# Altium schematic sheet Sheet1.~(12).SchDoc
size A3
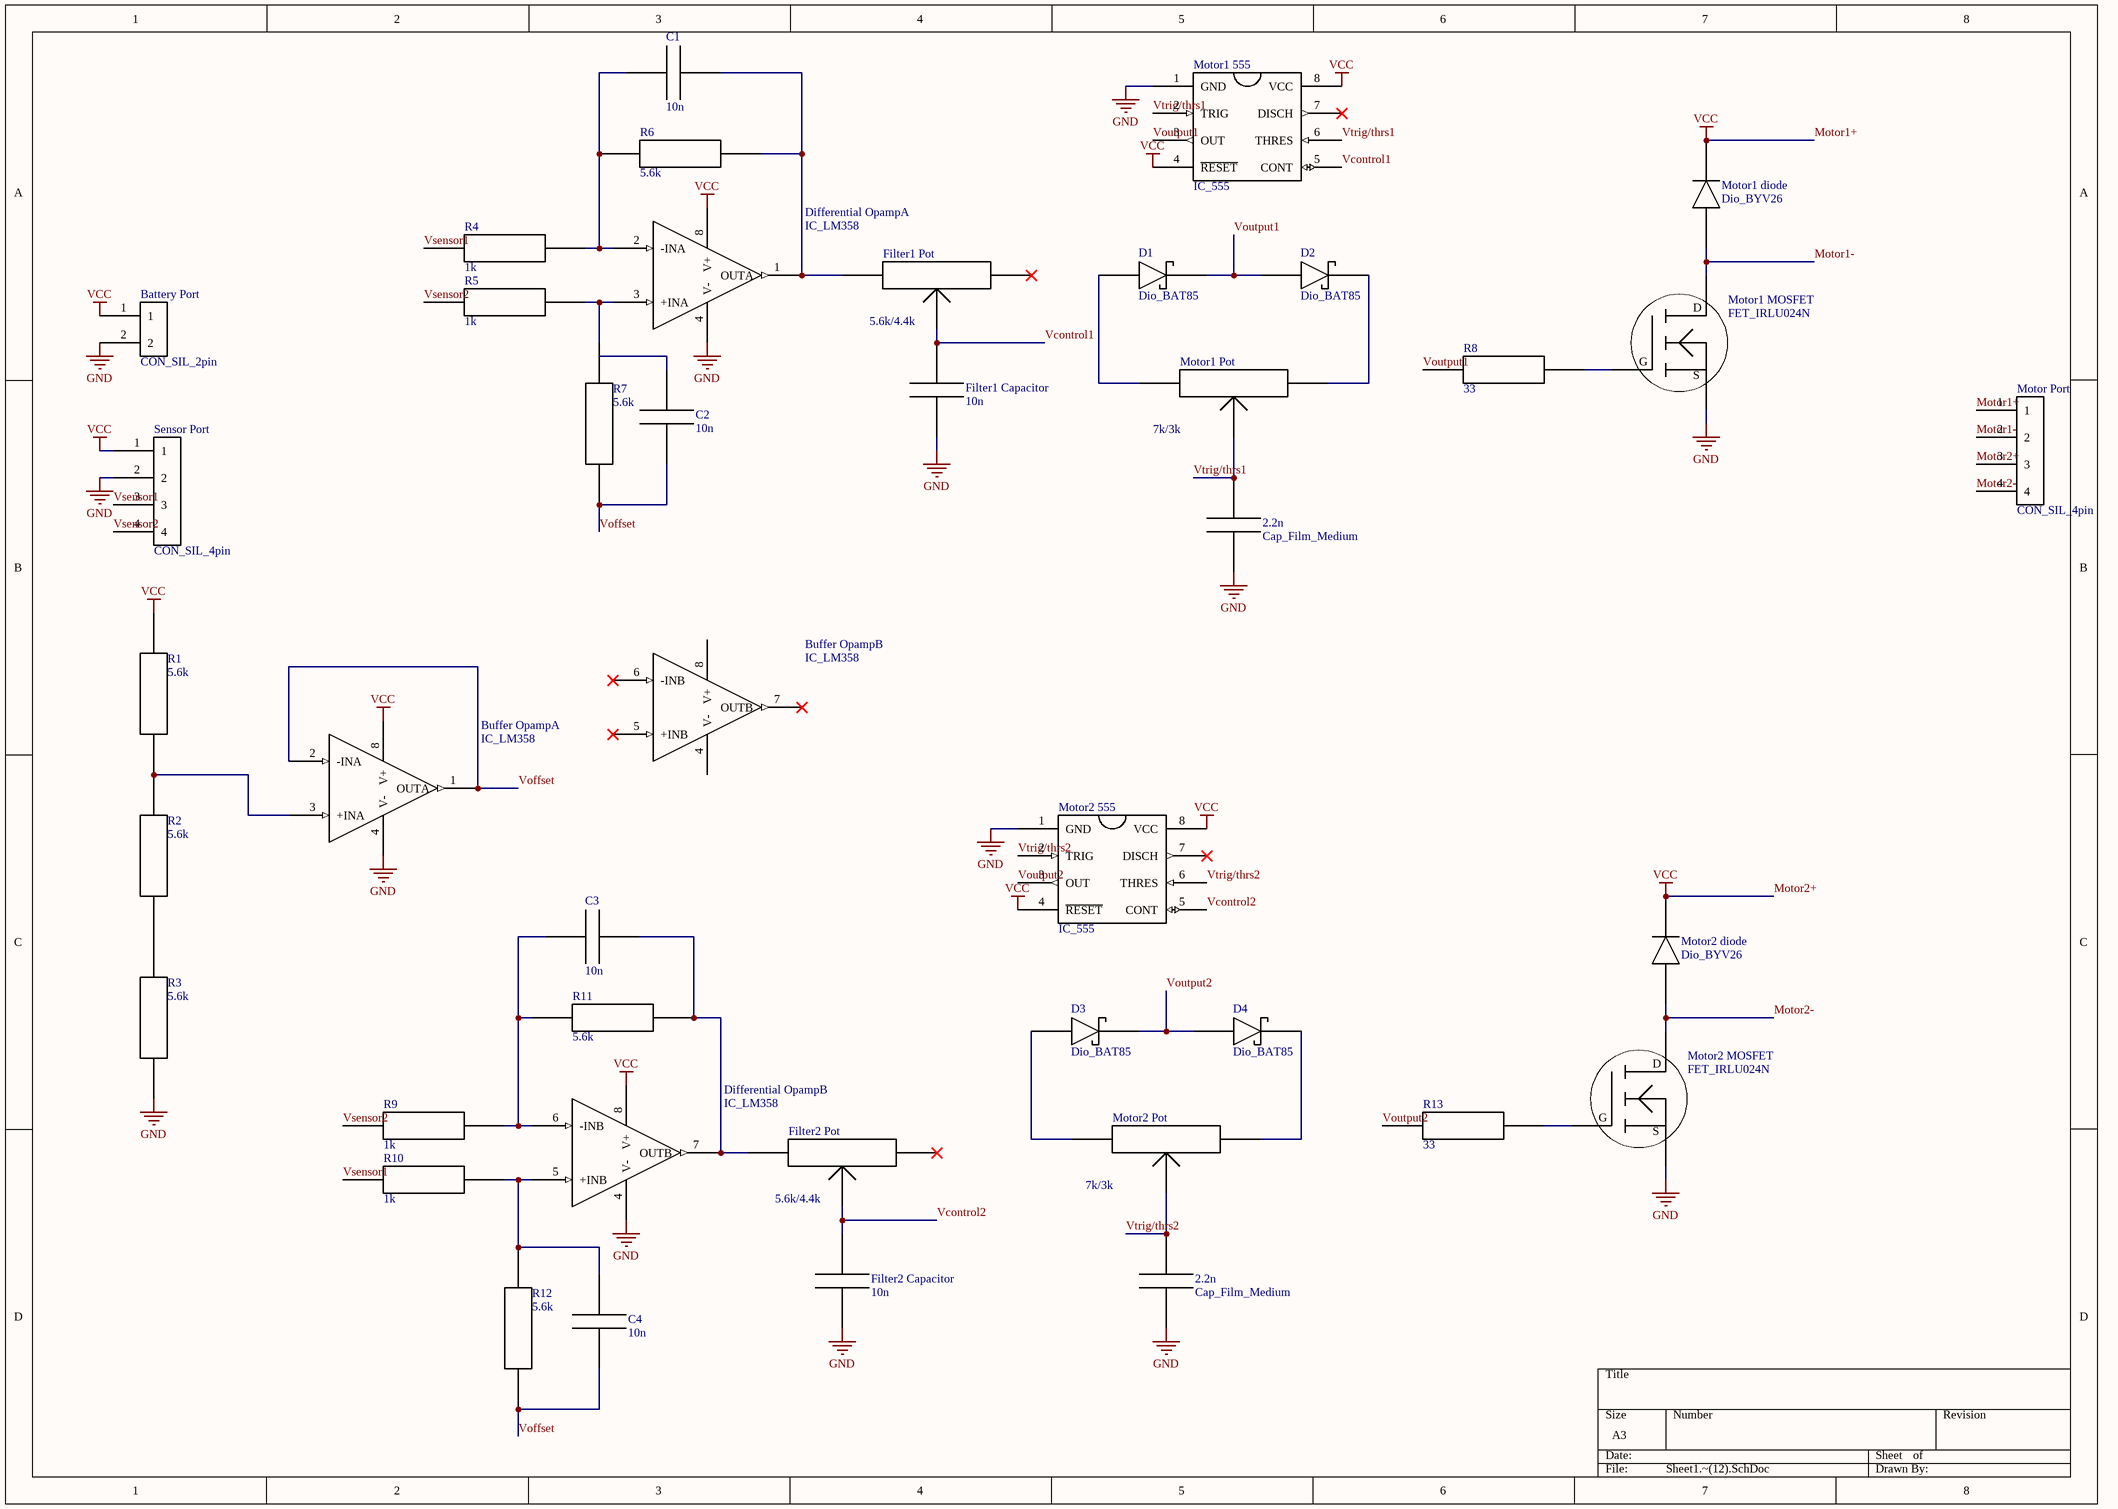
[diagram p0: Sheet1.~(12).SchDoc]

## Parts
(Parts that share a designator on the sheet are numbered #1, #2 ... from top to bottom, then left to right.)
2.2n#1  Cap_Film_Medium  [CAP_FILM_3.2mm]
2.2n#2  Cap_Film_Medium  [CAP_FILM_3.2mm]
Battery_Port  CON_SIL_2pin  [ece-HDR1X2]
Buffer_Opamp  IC_LM358  [DIP_8]  (parts A,B of 2)
C1  10n  [CAP_FILM_3.2mm]
C2  10n  [CAP_FILM_3.2mm]
C3  10n  [CAP_FILM_3.2mm]
C4  10n  [CAP_FILM_3.2mm]
D1  Dio_BAT85  [Diode_SmallSignal]
D2  Dio_BAT85  [Diode_SmallSignal]
D3  Dio_BAT85  [Diode_SmallSignal]
D4  Dio_BAT85  [Diode_SmallSignal]
Differential_Opamp  IC_LM358  [DIP_8]  (parts A,B of 2)
Filter1_Capacitor  10n  [CAP_FILM_3.2mm]
Filter1_Pot  5.6k/4.4k  [POT]
Filter2_Capacitor  10n  [CAP_FILM_3.2mm]
Filter2_Pot  5.6k/4.4k  [POT]
Motor1_555  IC_555  [DIP_8]
Motor1_diode  Dio_BYV26  [SOD_47]
Motor1_MOSFET  FET_IRLU024N  [TO_251AA]
Motor1_Pot  7k/3k  [POT]
Motor2_555  IC_555  [DIP_8]
Motor2_diode  Dio_BYV26  [SOD_47]
Motor2_MOSFET  FET_IRLU024N  [TO_251AA]
Motor2_Pot  7k/3k  [POT]
Motor_Port  CON_SIL_4pin  [ece-HDR1X4]
R1  5.6k  [Resistor_400mil_pitch]
R2  5.6k  [Resistor_400mil_pitch]
R3  5.6k  [Resistor_400mil_pitch]
R4  1k  [Resistor_400mil_pitch]
R5  1k  [Resistor_400mil_pitch]
R6  5.6k  [Resistor_400mil_pitch]
R7  5.6k  [Resistor_400mil_pitch]
R8  33  [Resistor_400mil_pitch]
R9  1k  [Resistor_400mil_pitch]
R10  1k  [Resistor_400mil_pitch]
R11  5.6k  [Resistor_400mil_pitch]
R12  5.6k  [Resistor_400mil_pitch]
R13  33  [Resistor_400mil_pitch]
Sensor_Port  CON_SIL_4pin  [ece-HDR1X4]

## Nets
GND: 2.2n#1.2 2.2n#2.2 Battery_Port.2 Buffer_Opamp.4(V-) Differential_Opamp.4(V-) Filter1_Capacitor.2 Filter2_Capacitor.2 Motor1_555.1(GND) Motor1_MOSFET.3(S) Motor2_555.1(GND) Motor2_MOSFET.3(S) R3.2 Sensor_Port.2
Motor1+: Battery_Port.1 Buffer_Opamp.8(V+) Differential_Opamp.8(V+) Motor1_555.4(~{RESET}) Motor1_555.8(VCC) Motor1_diode.2 Motor2_555.4(~{RESET}) Motor2_555.8(VCC) Motor2_diode.2 Motor_Port.1 Motor_Port.3 R1.1 Sensor_Port.1  [also labelled Motor2+, VCC]
Motor1-: Motor1_diode.1 Motor1_MOSFET.1(D) Motor_Port.2
Motor2-: Motor2_diode.1 Motor2_MOSFET.1(D) Motor_Port.4
Vcontrol1: Filter1_Capacitor.1 Filter1_Pot.2 Motor1_555.5(CONT)
Vcontrol2: Filter2_Capacitor.1 Filter2_Pot.2 Motor2_555.5(CONT)
Voffset: Buffer_Opamp.1(OUTA) Buffer_Opamp.2(-INA) C2.1 C4.1 R7.1 R12.1
Voutput1: D1.2 D2.1 Motor1_555.3(OUT) R8.2
Voutput2: D3.2 D4.1 Motor2_555.3(OUT) R13.2
Vsensor1: R4.1 R10.1 Sensor_Port.3
Vsensor2: R5.1 R9.1 Sensor_Port.4
Vtrig/thrs1: 2.2n#1.1 Motor1_555.2(TRIG) Motor1_555.6(THRES) Motor1_Pot.2
Vtrig/thrs2: 2.2n#2.1 Motor2_555.2(TRIG) Motor2_555.6(THRES) Motor2_Pot.2
NetBuffer_Opamp_3: Buffer_Opamp.3(+INA) R1.2 R2.1
NetC1_1: C1.1 Differential_Opamp.2(-INA) R4.2 R6.1
NetC1_2: C1.2 Differential_Opamp.1(OUTA) Filter1_Pot.3 R6.2
NetC3_1: C3.1 Differential_Opamp.7(OUTB) Filter2_Pot.3 R11.2
NetC3_2: C3.2 Differential_Opamp.6(-INB) R9.2 R11.1
NetC4_2: C4.2 Differential_Opamp.5(+INB) R10.2 R12.2
NetD1_1: D1.1 Motor1_Pot.3
NetD2_2: D2.2 Motor1_Pot.1
NetD3_1: D3.1 Motor2_Pot.3
NetD4_2: D4.2 Motor2_Pot.1
NetDifferential_Opamp_3: Differential_Opamp.3(+INA) R5.2 R7.2
NetMotor1_MOSFET_2: Motor1_MOSFET.2(G) R8.1
NetMotor2_MOSFET_2: Motor2_MOSFET.2(G) R13.1
NetR2_2: R2.2 R3.1

Not connected (* = marked no-connect by the designer): Buffer_Opamp 5(+INB)* 6(-INB)* 7(OUTB)*; C2 2; Filter1_Pot 1*; Filter2_Pot 1*; Motor1_555 7(DISCH)*; Motor2_555 7(DISCH)*

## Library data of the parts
2.2n#1 2.2n#2 C1-C4 Filter1_Capacitor Filter2_Capacitor = Cap_Film_Medium: Cap_Ceramic
Battery_Port = CON_SIL_2pin: 2 pin in line connector
Buffer_Opamp Differential_Opamp = IC_LM358: LM358 - Dual Opamp
Filter1_Pot Filter2_Pot Motor1_Pot Motor2_Pot = Res_Pot_10k
Motor1_555 Motor2_555 = IC_555: NEC555
Motor1_diode Motor2_diode = Dio_BYV26: BYV26
Motor1_MOSFET Motor2_MOSFET = FET_IRLU024N: N-Chan MOSFET 55V 17A 65mOhm
Motor_Port Sensor_Port = CON_SIL_4pin: 4 pin in line connector
R1-R13 = Res_0.25W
